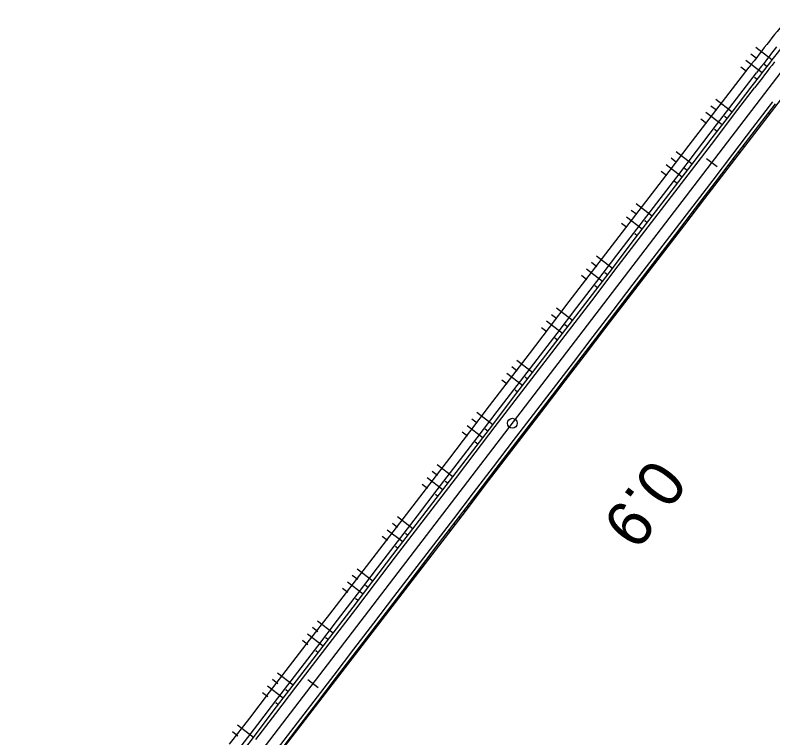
# Model space of a CAD drawing. Extents: x -481656 to -478728, y -1113199 to -1110710.
# Drawn here: x -479367.1 to -479251.7, y -1111179 to -1111068.9 of the extents above; entities that cross this region are included whole.
import ezdxf

# ---------------------------------------------------------------- set-up
doc = ezdxf.new("R2010")
doc.units = 0
for name, color, linetype in [('C5_HATCH_SLOPE_L', 7, 'Continuous'), ('C5_HATCH_SLOPE_R', 7, 'Continuous'), ('C5_HECTOMETRY', 7, 'Continuous'), ('C5_HRANA_TELESO', 7, 'Continuous'), ('C5_KORUNA', 7, 'Continuous'), ('C5_OSA', 7, 'Continuous'), ('C5_PRIKOP', 7, 'Continuous'), ('C5_STANICENI', 7, 'Continuous'), ('C5_ZPEVKRAJ', 7, 'Continuous')]:
    doc.layers.add(name, color=color, linetype=linetype)

msp = doc.modelspace()

# ---------------------------------------------------------------- linework, layer by layer
at = {"layer": 'C5_HATCH_SLOPE_L'}
for p, q in [((-479251.81, -1111075.71), (-479254.25, -1111073.84)), ((-479254.2, -1111075.46), (-479255.02, -1111074.83)), ((-479253.33, -1111077.7), (-479255.78, -1111075.83)), ((-479255.72, -1111077.45), (-479256.54, -1111076.82)), ((-479252.58, -1111076.71), (-479252.98, -1111076.4)), ((-479254.09, -1111078.69), (-479254.49, -1111078.39)), ((-479257.89, -1111083.66), (-479260.35, -1111081.77)), ((-479260.28, -1111083.4), (-479261.11, -1111082.77)), ((-479259.41, -1111085.64), (-479261.87, -1111083.76)), ((-479258.65, -1111084.65), (-479259.05, -1111084.34)), ((-479261.8, -1111085.39), (-479262.63, -1111084.75)), ((-479260.17, -1111086.63), (-479260.57, -1111086.33)), ((-479263.97, -1111091.6), (-479266.42, -1111089.72)), ((-479266.35, -1111091.35), (-479267.18, -1111090.71)), ((-479265.49, -1111093.58), (-479267.94, -1111091.71)), ((-479264.73, -1111092.59), (-479265.13, -1111092.28)), ((-479267.87, -1111093.33), (-479268.7, -1111092.7)), ((-479266.25, -1111094.57), (-479266.65, -1111094.27)), ((-479270.05, -1111099.54), (-479272.48, -1111097.67)), ((-479272.42, -1111099.29), (-479273.24, -1111098.67)), ((-479271.57, -1111101.52), (-479274, -1111099.66)), ((-479270.81, -1111100.53), (-479271.2, -1111100.23)), ((-479273.94, -1111101.28), (-479274.76, -1111100.65)), ((-479272.33, -1111102.51), (-479272.72, -1111102.21)), ((-479276.13, -1111107.48), (-479278.57, -1111105.61)), ((-479278.5, -1111107.24), (-479279.32, -1111106.6)), ((-479280.02, -1111109.22), (-479280.84, -1111108.59)), ((-479277.65, -1111109.46), (-479280.08, -1111107.6)), ((-479276.89, -1111108.47), (-479277.28, -1111108.17)), ((-479278.41, -1111110.46), (-479278.8, -1111110.15)), ((-479282.21, -1111115.42), (-479284.64, -1111113.56)), ((-479284.57, -1111115.18), (-479285.4, -1111114.55)), ((-479286.09, -1111117.17), (-479286.91, -1111116.54)), ((-479283.73, -1111117.4), (-479286.15, -1111115.55)), ((-479282.97, -1111116.41), (-479283.36, -1111116.11)), ((-479284.49, -1111118.4), (-479284.88, -1111118.1)), ((-479288.29, -1111123.36), (-479290.69, -1111121.52)), ((-479289.8, -1111125.34), (-479292.21, -1111123.5)), ((-479290.64, -1111123.13), (-479291.45, -1111122.51)), ((-479292.15, -1111125.12), (-479292.97, -1111124.5)), ((-479289.04, -1111124.35), (-479289.43, -1111124.05)), ((-479290.56, -1111126.34), (-479290.95, -1111126.04)), ((-479296.71, -1111131.08), (-479297.52, -1111130.46)), ((-479294.36, -1111131.3), (-479296.76, -1111129.46)), ((-479295.88, -1111133.28), (-479298.27, -1111131.45)), ((-479298.22, -1111133.07), (-479299.03, -1111132.45)), ((-479295.12, -1111132.29), (-479295.51, -1111132)), ((-479296.64, -1111134.28), (-479297.03, -1111133.98)), ((-479300.44, -1111139.24), (-479302.81, -1111137.43)), ((-479302.77, -1111139.03), (-479303.57, -1111138.42)), ((-479301.96, -1111141.22), (-479304.33, -1111139.41)), ((-479304.29, -1111141.02), (-479305.09, -1111140.41)), ((-479301.2, -1111140.23), (-479301.59, -1111139.94)), ((-479302.72, -1111142.22), (-479303.1, -1111141.92)), ((-479306.52, -1111147.18), (-479308.89, -1111145.36)), ((-479308.85, -1111146.97), (-479309.65, -1111146.35)), ((-479308.04, -1111149.17), (-479310.42, -1111147.35)), ((-479310.37, -1111148.96), (-479311.18, -1111148.34)), ((-479307.28, -1111148.17), (-479307.66, -1111147.88)), ((-479308.8, -1111150.16), (-479309.18, -1111149.87)), ((-479312.6, -1111155.12), (-479314.99, -1111153.29)), ((-479314.93, -1111154.91), (-479315.75, -1111154.28)), ((-479314.12, -1111157.11), (-479316.51, -1111155.27)), ((-479313.36, -1111156.11), (-479313.74, -1111155.82)), ((-479316.45, -1111156.89), (-479317.27, -1111156.27)), ((-479314.88, -1111158.1), (-479315.26, -1111157.81)), ((-479318.68, -1111163.06), (-479321.08, -1111161.22)), ((-479321.02, -1111162.84), (-479321.84, -1111162.21)), ((-479320.2, -1111165.05), (-479322.6, -1111163.2)), ((-479319.44, -1111164.05), (-479319.82, -1111163.76)), ((-479322.54, -1111164.83), (-479323.36, -1111164.2)), ((-479320.96, -1111166.04), (-479321.33, -1111165.75)), ((-479324.76, -1111171), (-479327.17, -1111169.15)), ((-479327.1, -1111170.78), (-479327.93, -1111170.14)), ((-479326.28, -1111172.99), (-479328.69, -1111171.14)), ((-479325.52, -1111171.99), (-479325.89, -1111171.71)), ((-479328.62, -1111172.77), (-479329.45, -1111172.13)), ((-479327.03, -1111173.98), (-479327.41, -1111173.69)), ((-479330.83, -1111178.94), (-479333.24, -1111177.1)), ((-479333.17, -1111178.73), (-479334.01, -1111178.09))]:
    msp.add_line(p, q, dxfattribs=at)
at = {"layer": 'C5_HATCH_SLOPE_R'}
for p, q in [((-479252.35, -1111083.82), (-479252.25, -1111083.89)), ((-479252.15, -1111083.97), (-479252.15, -1111083.97)), ((-479256.15, -1111088.78), (-479255.95, -1111088.93)), ((-479256.91, -1111089.77), (-479256.81, -1111089.85)), ((-479256.71, -1111089.92), (-479256.71, -1111089.92)), ((-479257.67, -1111090.76), (-479257.47, -1111090.91)), ((-479258.43, -1111091.76), (-479258.33, -1111091.83)), ((-479258.23, -1111091.91), (-479258.23, -1111091.91)), ((-479262.23, -1111096.72), (-479262.04, -1111096.86)), ((-479262.99, -1111097.71), (-479262.89, -1111097.78)), ((-479262.8, -1111097.86), (-479262.8, -1111097.86)), ((-479263.75, -1111098.71), (-479263.56, -1111098.85)), ((-479264.51, -1111099.7), (-479264.41, -1111099.77)), ((-479264.32, -1111099.84), (-479264.32, -1111099.84)), ((-479268.3, -1111104.66), (-479268.12, -1111104.8)), ((-479269.07, -1111105.65), (-479268.98, -1111105.72)), ((-479268.89, -1111105.79), (-479268.89, -1111105.79)), ((-479269.83, -1111106.65), (-479269.65, -1111106.78)), ((-479270.58, -1111107.64), (-479270.49, -1111107.71)), ((-479270.41, -1111107.77), (-479270.41, -1111107.77)), ((-479274.38, -1111112.6), (-479274.21, -1111112.73)), ((-479275.14, -1111113.59), (-479275.06, -1111113.66)), ((-479274.97, -1111113.72), (-479274.97, -1111113.72)), ((-479275.9, -1111114.59), (-479275.73, -1111114.72)), ((-479276.66, -1111115.58), (-479276.58, -1111115.64)), ((-479276.49, -1111115.71), (-479276.49, -1111115.71)), ((-479280.46, -1111120.54), (-479280.29, -1111120.67)), ((-479281.22, -1111121.53), (-479281.14, -1111121.6)), ((-479281.05, -1111121.66), (-479281.05, -1111121.66)), ((-479282.74, -1111123.52), (-479282.66, -1111123.58)), ((-479281.98, -1111122.53), (-479281.81, -1111122.66)), ((-479282.57, -1111123.65), (-479282.57, -1111123.65)), ((-479286.54, -1111128.48), (-479286.37, -1111128.61)), ((-479288.06, -1111130.47), (-479287.89, -1111130.6)), ((-479287.3, -1111129.47), (-479287.22, -1111129.54)), ((-479287.13, -1111129.6), (-479287.13, -1111129.6)), ((-479288.82, -1111131.46), (-479288.74, -1111131.52)), ((-479288.65, -1111131.59), (-479288.65, -1111131.59)), ((-479293.38, -1111137.42), (-479293.3, -1111137.48)), ((-479292.62, -1111136.42), (-479292.45, -1111136.55)), ((-479294.14, -1111138.41), (-479293.97, -1111138.53)), ((-479293.21, -1111137.54), (-479293.21, -1111137.54)), ((-479294.9, -1111139.4), (-479294.82, -1111139.46)), ((-479294.73, -1111139.53), (-479294.73, -1111139.53)), ((-479298.7, -1111144.36), (-479298.49, -1111144.52)), ((-479299.46, -1111145.36), (-479299.35, -1111145.43)), ((-479299.25, -1111145.51), (-479299.25, -1111145.51)), ((-479300.22, -1111146.35), (-479300.02, -1111146.5)), ((-479300.98, -1111147.34), (-479300.88, -1111147.42)), ((-479300.78, -1111147.49), (-479300.78, -1111147.49)), ((-479304.78, -1111152.3), (-479304.6, -1111152.44)), ((-479305.54, -1111153.3), (-479305.45, -1111153.36)), ((-479305.36, -1111153.43), (-479305.36, -1111153.43)), ((-479306.29, -1111154.29), (-479306.12, -1111154.42)), ((-479307.05, -1111155.28), (-479306.97, -1111155.35)), ((-479306.89, -1111155.41), (-479306.89, -1111155.41)), ((-479310.85, -1111160.24), (-479310.7, -1111160.36)), ((-479311.61, -1111161.24), (-479311.54, -1111161.29)), ((-479311.46, -1111161.35), (-479311.46, -1111161.35)), ((-479312.37, -1111162.23), (-479312.22, -1111162.34)), ((-479313.13, -1111163.22), (-479313.06, -1111163.28)), ((-479312.99, -1111163.33), (-479312.99, -1111163.33)), ((-479316.93, -1111168.19), (-479316.8, -1111168.29)), ((-479317.69, -1111169.18), (-479317.62, -1111169.23)), ((-479317.56, -1111169.28), (-479317.56, -1111169.28)), ((-479318.45, -1111170.17), (-479318.32, -1111170.27)), ((-479319.21, -1111171.16), (-479319.15, -1111171.21)), ((-479319.08, -1111171.26), (-479319.08, -1111171.26)), ((-479323.01, -1111176.13), (-479322.89, -1111176.22)), ((-479323.77, -1111177.12), (-479323.71, -1111177.16)), ((-479323.65, -1111177.21), (-479323.65, -1111177.21)), ((-479324.53, -1111178.11), (-479324.42, -1111178.2))]:
    msp.add_line(p, q, dxfattribs=at)
at = {"layer": 'C5_HECTOMETRY'}
msp.add_circle((-479291.37, -1111131.08), 0.75, dxfattribs=at)
at = {"layer": 'C5_HRANA_TELESO'}
for p, q in [((-479258.35, -1111080.8), (-479255.29, -1111076.84)), ((-479261.39, -1111084.76), (-479258.35, -1111080.8)), ((-479252.91, -1111084.96), (-479249.86, -1111081)), ((-479264.44, -1111088.73), (-479261.39, -1111084.76)), ((-479255.95, -1111088.93), (-479252.91, -1111084.96)), ((-479267.47, -1111092.7), (-479264.44, -1111088.73)), ((-479258.99, -1111092.9), (-479255.95, -1111088.93)), ((-479270.51, -1111096.68), (-479267.47, -1111092.7)), ((-479262.04, -1111096.86), (-479258.99, -1111092.9)), ((-479273.55, -1111100.64), (-479270.51, -1111096.68)), ((-479265.08, -1111100.83), (-479262.04, -1111096.86)), ((-479276.6, -1111104.61), (-479273.55, -1111100.64)), ((-479268.12, -1111104.8), (-479265.08, -1111100.83)), ((-479279.65, -1111108.57), (-479276.6, -1111104.61)), ((-479271.17, -1111108.77), (-479268.12, -1111104.8)), ((-479282.69, -1111112.54), (-479279.65, -1111108.57)), ((-479274.21, -1111112.73), (-479271.17, -1111108.77)), ((-479285.72, -1111116.51), (-479282.69, -1111112.54)), ((-479277.26, -1111116.7), (-479274.21, -1111112.73)), ((-479288.76, -1111120.49), (-479285.72, -1111116.51)), ((-479280.29, -1111120.67), (-479277.26, -1111116.7)), ((-479291.79, -1111124.46), (-479288.76, -1111120.49)), ((-479283.33, -1111124.64), (-479280.29, -1111120.67)), ((-479294.83, -1111128.43), (-479291.79, -1111124.46)), ((-479286.37, -1111128.61), (-479283.33, -1111124.64)), ((-479297.87, -1111132.41), (-479294.83, -1111128.43)), ((-479289.42, -1111132.58), (-479286.37, -1111128.61)), ((-479300.9, -1111136.38), (-479297.87, -1111132.41)), ((-479292.45, -1111136.55), (-479289.42, -1111132.58)), ((-479303.93, -1111140.36), (-479300.9, -1111136.38)), ((-479295.49, -1111140.52), (-479292.45, -1111136.55)), ((-479306.98, -1111144.32), (-479303.93, -1111140.36)), ((-479298.49, -1111144.52), (-479295.49, -1111140.52)), ((-479310.04, -1111148.28), (-479306.98, -1111144.32)), ((-479301.54, -1111148.48), (-479298.49, -1111144.52)), ((-479313.09, -1111152.24), (-479310.04, -1111148.28)), ((-479304.6, -1111152.44), (-479301.54, -1111148.48)), ((-479316.14, -1111156.2), (-479313.09, -1111152.24)), ((-479307.65, -1111156.4), (-479304.6, -1111152.44)), ((-479319.19, -1111160.16), (-479316.14, -1111156.2)), ((-479310.7, -1111160.36), (-479307.65, -1111156.4)), ((-479322.25, -1111164.12), (-479319.19, -1111160.16)), ((-479313.75, -1111164.32), (-479310.7, -1111160.36)), ((-479325.3, -1111168.08), (-479322.25, -1111164.12)), ((-479316.8, -1111168.29), (-479313.75, -1111164.32)), ((-479328.35, -1111172.04), (-479325.3, -1111168.08)), ((-479319.84, -1111172.25), (-479316.8, -1111168.29)), ((-479331.39, -1111176.01), (-479328.35, -1111172.04)), ((-479322.89, -1111176.22), (-479319.84, -1111172.25)), ((-479334.44, -1111179.97), (-479331.39, -1111176.01)), ((-479325.94, -1111180.18), (-479322.89, -1111176.22))]:
    msp.add_line(p, q, dxfattribs=at)
for centre, radius, start, end in [((-479013.18, -1111261.17), 304.29, 140.814, 141.769), ((-478533.23, -1111635.43), 912.91, 141.95827, 142.27443)]:
    msp.add_arc(centre, radius, start, end, dxfattribs=at)
at = {"layer": 'C5_KORUNA'}
for p, q in [((-479257.89, -1111083.66), (-479254.85, -1111079.69)), ((-479254.32, -1111086.39), (-479251.28, -1111082.42)), ((-479260.93, -1111087.62), (-479257.89, -1111083.66)), ((-479257.36, -1111090.36), (-479254.32, -1111086.39)), ((-479263.97, -1111091.6), (-479260.93, -1111087.62)), ((-479260.4, -1111094.33), (-479257.36, -1111090.36)), ((-479267.01, -1111095.57), (-479263.97, -1111091.6)), ((-479263.44, -1111098.3), (-479260.4, -1111094.33)), ((-479270.05, -1111099.54), (-479267.01, -1111095.57)), ((-479266.48, -1111102.27), (-479263.44, -1111098.3)), ((-479273.09, -1111103.51), (-479270.05, -1111099.54)), ((-479269.52, -1111106.24), (-479266.48, -1111102.27)), ((-479276.13, -1111107.48), (-479273.09, -1111103.51)), ((-479272.55, -1111110.21), (-479269.52, -1111106.24)), ((-479279.17, -1111111.45), (-479276.13, -1111107.48)), ((-479275.59, -1111114.18), (-479272.55, -1111110.21)), ((-479282.21, -1111115.42), (-479279.17, -1111111.45)), ((-479278.63, -1111118.15), (-479275.59, -1111114.18)), ((-479285.25, -1111119.39), (-479282.21, -1111115.42)), ((-479281.67, -1111122.12), (-479278.63, -1111118.15)), ((-479288.29, -1111123.36), (-479285.25, -1111119.39)), ((-479284.71, -1111126.09), (-479281.67, -1111122.12)), ((-479291.32, -1111127.33), (-479288.29, -1111123.36)), ((-479287.75, -1111130.06), (-479284.71, -1111126.09)), ((-479294.36, -1111131.3), (-479291.32, -1111127.33)), ((-479290.79, -1111134.03), (-479287.75, -1111130.06)), ((-479297.4, -1111135.27), (-479294.36, -1111131.3)), ((-479293.83, -1111138), (-479290.79, -1111134.03)), ((-479300.44, -1111139.24), (-479297.4, -1111135.27)), ((-479296.87, -1111141.98), (-479293.83, -1111138)), ((-479303.48, -1111143.21), (-479300.44, -1111139.24)), ((-479299.91, -1111145.95), (-479296.87, -1111141.98)), ((-479306.52, -1111147.18), (-479303.48, -1111143.21)), ((-479302.95, -1111149.92), (-479299.91, -1111145.95)), ((-479309.56, -1111151.15), (-479306.52, -1111147.18)), ((-479305.99, -1111153.89), (-479302.95, -1111149.92)), ((-479312.6, -1111155.12), (-479309.56, -1111151.15)), ((-479309.03, -1111157.86), (-479305.99, -1111153.89)), ((-479315.64, -1111159.09), (-479312.6, -1111155.12)), ((-479312.06, -1111161.83), (-479309.03, -1111157.86)), ((-479318.68, -1111163.06), (-479315.64, -1111159.09)), ((-479315.1, -1111165.8), (-479312.06, -1111161.83)), ((-479321.72, -1111167.03), (-479318.68, -1111163.06)), ((-479318.14, -1111169.77), (-479315.1, -1111165.8)), ((-479324.76, -1111171), (-479321.72, -1111167.03)), ((-479321.18, -1111173.74), (-479318.14, -1111169.77)), ((-479327.79, -1111174.97), (-479324.76, -1111171)), ((-479324.22, -1111177.71), (-479321.18, -1111173.74)), ((-479330.83, -1111178.94), (-479327.79, -1111174.97)), ((-479327.26, -1111181.68), (-479324.22, -1111177.71)), ((-479333.87, -1111182.91), (-479330.83, -1111178.94))]:
    msp.add_line(p, q, dxfattribs=at)
for centre, radius, start, end in [((-479012.18, -1111259.92), 302.25, 141.4954, 142.4503), ((-478533.39, -1111628.94), 906.75, 142.40159, 142.71782)]:
    msp.add_arc(centre, radius, start, end, dxfattribs=at)
at = {"layer": 'C5_OSA'}
msp.add_line((-479472.65, -1111367.92), (-479250.4, -1111077.57), dxfattribs=at)
at = {"layer": 'C5_PRIKOP'}
for p, q in [((-479257.21, -1111081.67), (-479254.17, -1111077.7)), ((-479260.25, -1111085.64), (-479257.21, -1111081.67)), ((-479263.29, -1111089.61), (-479260.25, -1111085.64)), ((-479266.33, -1111093.58), (-479263.29, -1111089.61)), ((-479269.37, -1111097.55), (-479266.33, -1111093.58)), ((-479272.41, -1111101.52), (-479269.37, -1111097.55)), ((-479275.45, -1111105.49), (-479272.41, -1111101.52)), ((-479278.49, -1111109.46), (-479275.45, -1111105.49)), ((-479281.53, -1111113.43), (-479278.49, -1111109.46)), ((-479284.56, -1111117.4), (-479281.53, -1111113.43)), ((-479287.6, -1111121.37), (-479284.56, -1111117.4)), ((-479290.64, -1111125.34), (-479287.6, -1111121.37)), ((-479293.68, -1111129.31), (-479290.64, -1111125.34)), ((-479296.72, -1111133.28), (-479293.68, -1111129.31)), ((-479299.76, -1111137.25), (-479296.72, -1111133.28)), ((-479302.8, -1111141.22), (-479299.76, -1111137.25)), ((-479305.84, -1111145.19), (-479302.8, -1111141.22)), ((-479308.88, -1111149.16), (-479305.84, -1111145.19)), ((-479311.92, -1111153.13), (-479308.88, -1111149.16)), ((-479314.96, -1111157.1), (-479311.92, -1111153.13)), ((-479317.99, -1111161.07), (-479314.96, -1111157.1)), ((-479321.03, -1111165.04), (-479317.99, -1111161.07)), ((-479324.07, -1111169.02), (-479321.03, -1111165.04)), ((-479327.11, -1111172.99), (-479324.07, -1111169.02)), ((-479330.15, -1111176.96), (-479327.11, -1111172.99)), ((-479333.19, -1111180.93), (-479330.15, -1111176.96))]:
    msp.add_line(p, q, dxfattribs=at)
msp.add_arc((-478532.29, -1111629.71), 908.75, 142.27851, 142.59535, dxfattribs=at)
at = {"layer": 'C5_STANICENI'}
for p, q in [((-479260.18, -1111091.99), (-479261.77, -1111090.77)), ((-479320.96, -1111171.4), (-479322.55, -1111170.18))]:
    msp.add_line(p, q, dxfattribs=at)
at = {"layer": 'C5_ZPEVKRAJ'}
for p, q in [((-479257.5, -1111083.96), (-479254.46, -1111079.99)), ((-479254.72, -1111086.09), (-479251.68, -1111082.12)), ((-479260.54, -1111087.93), (-479257.5, -1111083.96)), ((-479257.76, -1111090.06), (-479254.72, -1111086.09)), ((-479263.57, -1111091.9), (-479260.54, -1111087.93)), ((-479260.79, -1111094.03), (-479257.76, -1111090.06)), ((-479266.61, -1111095.87), (-479263.57, -1111091.9)), ((-479263.83, -1111098), (-479260.79, -1111094.03)), ((-479269.65, -1111099.84), (-479266.61, -1111095.87)), ((-479266.87, -1111101.97), (-479263.83, -1111098)), ((-479272.69, -1111103.81), (-479269.65, -1111099.84)), ((-479269.91, -1111105.94), (-479266.87, -1111101.97)), ((-479275.73, -1111107.78), (-479272.69, -1111103.81)), ((-479272.95, -1111109.91), (-479269.91, -1111105.94)), ((-479278.77, -1111111.75), (-479275.73, -1111107.78)), ((-479275.99, -1111113.88), (-479272.95, -1111109.91)), ((-479281.81, -1111115.72), (-479278.77, -1111111.75)), ((-479279.03, -1111117.85), (-479275.99, -1111113.88)), ((-479284.85, -1111119.69), (-479281.81, -1111115.72)), ((-479282.07, -1111121.82), (-479279.03, -1111117.85)), ((-479287.89, -1111123.66), (-479284.85, -1111119.69)), ((-479285.11, -1111125.79), (-479282.07, -1111121.82)), ((-479290.93, -1111127.63), (-479287.89, -1111123.66)), ((-479288.15, -1111129.76), (-479285.11, -1111125.79)), ((-479293.97, -1111131.6), (-479290.93, -1111127.63)), ((-479291.19, -1111133.73), (-479288.15, -1111129.76)), ((-479297.01, -1111135.57), (-479293.97, -1111131.6)), ((-479294.23, -1111137.7), (-479291.19, -1111133.73)), ((-479300.04, -1111139.54), (-479297.01, -1111135.57)), ((-479297.27, -1111141.67), (-479294.23, -1111137.7)), ((-479303.08, -1111143.51), (-479300.04, -1111139.54)), ((-479300.3, -1111145.64), (-479297.27, -1111141.67)), ((-479306.12, -1111147.48), (-479303.08, -1111143.51)), ((-479303.34, -1111149.61), (-479300.3, -1111145.64)), ((-479309.16, -1111151.45), (-479306.12, -1111147.48)), ((-479306.38, -1111153.58), (-479303.34, -1111149.61)), ((-479312.2, -1111155.43), (-479309.16, -1111151.45)), ((-479309.42, -1111157.55), (-479306.38, -1111153.58)), ((-479315.24, -1111159.4), (-479312.2, -1111155.43)), ((-479312.46, -1111161.52), (-479309.42, -1111157.55)), ((-479318.28, -1111163.36), (-479315.24, -1111159.4)), ((-479315.5, -1111165.49), (-479312.46, -1111161.52)), ((-479321.32, -1111167.33), (-479318.28, -1111163.36)), ((-479318.54, -1111169.46), (-479315.5, -1111165.49)), ((-479324.36, -1111171.31), (-479321.32, -1111167.33)), ((-479321.58, -1111173.43), (-479318.54, -1111169.46)), ((-479327.4, -1111175.28), (-479324.36, -1111171.31)), ((-479324.62, -1111177.4), (-479321.58, -1111173.43)), ((-479330.44, -1111179.25), (-479327.4, -1111175.28)), ((-479327.66, -1111181.37), (-479324.62, -1111177.4))]:
    msp.add_line(p, q, dxfattribs=at)
msp.add_arc((-478534.18, -1111628.33), 905.25, 142.40137, 142.71806, dxfattribs=at)

# ---------------------------------------------------------------- texts
at = {"layer": 'C5_HECTOMETRY'}
msp.add_text('0.9', height=7, rotation=232.5212, dxfattribs=at).set_placement((-479269.98, -1111136.07))

doc.saveas('drawing.dxf')
